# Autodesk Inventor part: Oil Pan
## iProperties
Author: lebovipa
Shininess: 25.0
PropertySet Name: _Private Model Information
Created: 2000-11
Part Number: Oil Pan
Document SubType Name: Modeling
Designer: lebovipa
Control State: 0
Master: False
Checked Out: False
PropertySet Name: Design Tracking Control
Density: 0.0
Volumn: 0.0
Area: 0.0
PropertySet Name: Model Information
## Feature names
1. Extrusion1
2. Extrusion2
3. TaperEdge1
4. Split1
5. TaperEdge5
6. TaperEdge4
7. TaperEdge7
8. Fillet4
9. Fillet1
10. Fillet2
11. Shell1
12. Extrusion6
13. Mirror1
14. Extrusion7
15. Mirror2
16. Shell4
17. Fillet10
18. Hole1
19. Fillet11
20. Fillet12
21. Extrusion8
22. Fillet13
23. Hole2
